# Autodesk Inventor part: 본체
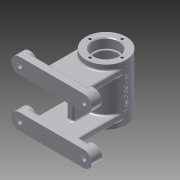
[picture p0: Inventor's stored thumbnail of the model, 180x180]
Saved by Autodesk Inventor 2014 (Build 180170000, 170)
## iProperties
Created: 2015-11
Part Number: 본체
Material: Aluminum 6061
Document SubType Name: Modeling
Designer: user
Mass: 357.945 g
Surface Area: 464.058 cm^2
Volume: 132.083 cm^3
Density: 2.71 g/cm^3
Appearance: Aluminum - Flat
Author: user
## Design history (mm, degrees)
sketch "Sketch1"
  geometry: C1 r 25 at (0, 0); 1 further point
  constraints: 1 centre point, 1 coincident
  dimensions: "d0" = 50 diameter of C1
extrude "Extrusion1" new body sketch "Sketch1" stored distance "d1" = 70; taper "d2" = 0 deg
workplane "Work Plane1"
sketch "Sketch2"
  geometry: L1 (40, -40)-(-40, -40); L2 (-40, -40)-(-40, -20); L3 (-40, -20)-(40, -20); L4 (40, -20)-(40, -40); L5 (40, 20)-(-40, 20); L6 (-40, 20)-(-40, 40); L7 (-40, 40)-(40, 40); L8 (40, 40)-(40, 20); 3 further points
  constraints: 16 end point, 4 parallel, 2 equal length, 2 horizontal, 2 midpoint, 2 perpendicular, 2 vertical alignment
  dimensions: "d4" = 40 distance from line of L1 point (0, 0); "d5" = 20 distance of L1.end L2.end; "d6" = 80 distance of L1.start L1.end; "d7" = 40 distance from line of L7 point (0, 0)
extrude "Extrusion2" join sketch "Sketch2" distance "d8" = 10; taper "d9" = 0 deg
sketch "Sketch3"
  geometry: L1 (40, 20)-(40, 40) reference; L2 (-40, 40)-(-40, 20) reference; L3 (-40, -40)-(40, -40) reference; L4 (40, -40)-(40, -20) reference; L5 (40, -20)-(-40, -20) reference; L6 (-40, -20)-(-40, -40) reference; C1 r 10 at (40, 30); C2 r 10 at (-40, 30); C3 r 10 at (40, -30); C4 r 10 at (-40, -30); 1 further point
  constraints: 4 centre point, 4 midpoint
  dimensions: "d10" = 20 diameter of C1; "d11" = 20 diameter of C2; "d12" = 20 diameter of C3; "d13" = 20 diameter of C4
extrude "Extrusion3" join sketch "Sketch3" distance "d14" = 13; taper "d15" = 0 deg
sketch "Sketch4"
  geometry: L1 (40, -20)-(-40, -20) reference; L2 (25, -20)-(-25, -20); L3 (-25, -20)-(-25, -28); L4 (-25, -28)-(25, -28); L5 (25, -28)-(25, -20); L6 (25, 28)-(-25, 28); L7 (-25, 28)-(-25, 20); L8 (-25, 20)-(25, 20); L9 (25, 20)-(25, 28); L10 (40, 20)-(-40, 20) reference; 5 further points
  constraints: 16 end point, 4 midpoint, 4 parallel, 2 coincident, 2 horizontal, 2 perpendicular, 2 vertical alignment
  dimensions: "d16" = 8 distance of L8.end L6.start; "d17" = 8 distance of L4.end L2.start; "d18" = 50 distance of L3.end L4.end; "d19" = 50 distance of L6.start L6.end
extrude "Extrusion4" join sketch "Sketch4" stored distance "d20" = 13; taper "d21" = 0 deg
workplane "Work Plane2"
sketch "Sketch5"
  geometry: L1 (40, 20)-(-40, 20) reference; L2 (-40, -20)-(40, -20) reference; L3 (-4, 20)-(4, 20); L4 (4, 20)-(4, -20); L5 (4, -20)-(-4, -20); L6 (-4, -20)-(-4, 20); 2 further points
  constraints: 8 end point, 2 parallel, 2 point on line, 1 horizontal, 1 midpoint, 1 perpendicular, 1 vertical alignment
  dimensions: "d23" = 8 distance between parallel lines of L6 L4
extrude "Extrusion5" join sketch "Sketch5" stored distance "d24" = 13; taper "d25" = 0 deg
sketch "Sketch6"
  geometry: L1 (40, 0)-(0, 0) reference; L2 (40, 20.322)-(40, 0) reference; L3 (12, 6.5)-(28, 6.5); L4 (28, 13.5)-(12, 13.5); A1 r 3.5 centre (28, 10) between (28, 6.5) and (28, 13.5); A2 r 3.5 centre (12, 10) between (12, 13.5) and (12, 6.5); 2 further points
  constraints: 4 end point, 4 point on circle, 3 tangent, 2 centre point, 1 equal radius, 1 midpoint, 1 parallel, 1 perpendicular, 1 vertical alignment
  dimensions: "d26" = 23 dimension on A1 A2; "d27" = 3.5 radius of A1; "d28" = 10 distance from line of A1.centre L1
extrude "Extrusion6" cut sketch "Sketch6" stored distance "d29" = 13; taper "d30" = 0 deg
workplane "Work Plane3"
sketch "Sketch7"
  geometry: C1 r 5 at (0, 0); 1 further point
  constraints: 1 centre point, 1 coincident
  dimensions: "d32" = 10 diameter of C1
extrude "Extrusion7" join sketch "Sketch7" stored distance "d33" = 13; taper "d34" = 0 deg
sketch "Sketch8"
  geometry: C1 r 25 at (0, 0) reference; C2 r 16 at (0, 0)
  constraints: 1 centre point, 1 coincident
  dimensions: "d35" = 32 diameter of C2
extrude "Extrusion8" cut sketch "Sketch8" distance "d36" = 12; taper "d37" = 0 deg
sketch "Sketch9"
  geometry: C1 r 16 at (0, 0) reference; C2 r 14 at (0, 0)
  constraints: 1 centre point, 1 coincident
  dimensions: "d38" = 28 diameter of C2
extrude "Extrusion9" cut sketch "Sketch9" distance "d39" = 2; taper "d40" = 0 deg
sketch "Sketch10"
  geometry: C1 r 16 at (0, 0) reference; 1 further point
  constraints: 1 vertical alignment
  dimensions: "d41" = 20 distance of C1.centre point (0, 20)
hole "Hole1" sketch "Sketch10" at (0, 20) diameter "d42" = 3.242; stored, may be unused: countersink angle "d46" = 90 deg, drill point angle "d48" = 118 deg; dims "d43" = 8, "d44" = 4, "d45" = 2, "d47" = 10
pattern_circular "Circular Pattern1" dims angle "d50" = 360 deg
mirror "Mirror1"
sketch "Sketch11"
  geometry: C1 r 14 at (0, 0) reference; C2 r 21 at (0, 0)
  constraints: 1 centre point, 1 coincident
  dimensions: "d52" = 42 diameter of C2
extrude "Extrusion10" cut sketch "Sketch11" distance "d53" = 42; taper "d54" = 0 deg
sketch "Sketch12"
  geometry: L1 (0, 0)-(-12.5, -21.651); L2 (0, 0)-(25, 0); 2 further points
  constraints: 4 end point, 1 coincident, 1 equal length, 1 horizontal, 2 other
  dimensions: "d55" = 120 deg angle of L1 L2
workplane "Work Plane5"
  workplane "Work Plane4"
sketch "Sketch13"
  geometry: C1 r 6 at (0, 0); 1 further point
  constraints: 1 centre point, 1 coincident
  dimensions: "d57" = 12 diameter of C1
extrude "Extrusion11" join sketch "Sketch13" stored distance "d58" = 42; taper "d59" = 0 deg
sketch "Sketch14"
  geometry: C1 r 5 at (0, 0) reference; 1 further point
  constraints: 1 coincident
hole "Hole2" sketch "Sketch14" at (0, 0) diameter "d60" = 5.188; stored, may be unused: countersink angle "d64" = 90 deg, drill point angle "d66" = 118 deg; dims "d61" = 8, "d62" = 4, "d63" = 2, "d65" = 10
sketch "Sketch15"
  geometry: C1 r 6 at (0, 0) reference; 1 further point
  constraints: 1 coincident
hole "Hole3" sketch "Sketch15" at (0, 0) diameter "d67" = 5.188; stored, may be unused: countersink angle "d71" = 90 deg, drill point angle "d73" = 118 deg; dims "d68" = 8, "d69" = 4, "d70" = 2, "d72" = 10
workplane "Work Plane6"
sketch "Sketch16"
  geometry: L1 (25, 35)-(-25, 35) reference; 2 further points
  constraints: 1 other
  dimensions: "d75" = 35 distance from line of point (0, 0) L1; "d76" = 25 horizontal distance of point (0, 0) L1.start
emboss "Emboss1" sketch "Sketch16" dims "d77" = 0.5, "d78" = 0
sketch "Sketch17"
  geometry: C1 r 10 at (0, 0) reference; C2 r 10 at (80, 0) reference; C3 r 10 at (80, -60) reference; C4 r 10 at (0, -60) reference; 5 further points
  constraints: 4 coincident
hole "Hole4" sketch "Sketch17" at (80, 0), (0, 0), (0, -60), (80, -60) diameter "d79" = 6; stored, may be unused: countersink angle "d83" = 90 deg, drill point angle "d85" = 0 deg; dims "d80" = 8.608, "d81" = 12, "d82" = 4, "d84" = 4
fillet "Fillet1" dims "d86" = 2
fillet "Fillet2" dims "d87" = 2
fillet "Fillet3" dims "d88" = 2
fillet "Fillet4" dims "d89" = 2, "d90" = 0.3
chamfer "Chamfer1" distance "d91" = 1; stored, may be unused: second distance "d92" = 2, angle "d93" = 45 deg
chamfer "Chamfer2" distance "d94" = 1; stored, may be unused: second distance "d95" = 2, angle "d96" = 45 deg
body "Solid1"
node "Projected Loop1"
node "Projected Loop2"
node "Projected Loop3"
node "Projected Loop4"
node "Projected Loop5"
other parameters: "d3" = -68, "d22" = -45, "d31" = 28, "d56" = 3, "d74" = 25
